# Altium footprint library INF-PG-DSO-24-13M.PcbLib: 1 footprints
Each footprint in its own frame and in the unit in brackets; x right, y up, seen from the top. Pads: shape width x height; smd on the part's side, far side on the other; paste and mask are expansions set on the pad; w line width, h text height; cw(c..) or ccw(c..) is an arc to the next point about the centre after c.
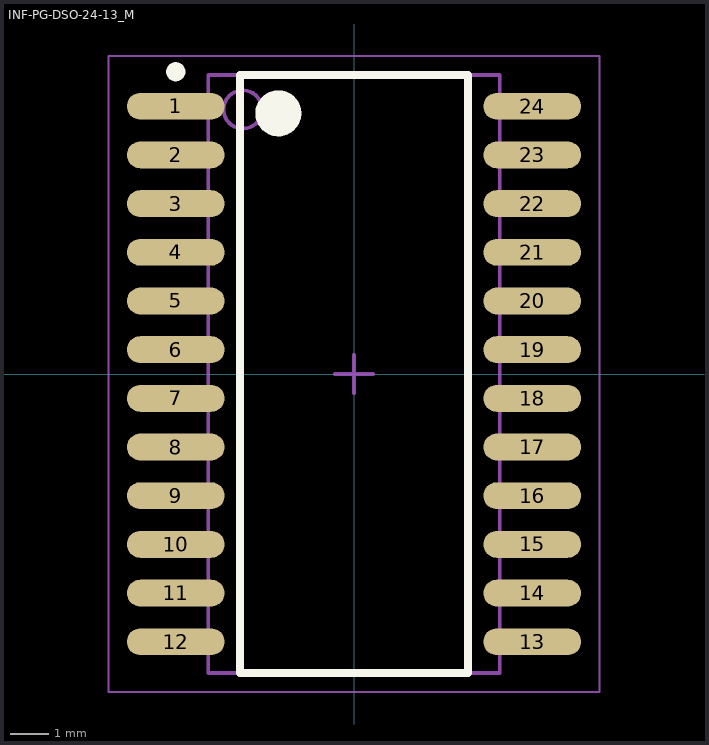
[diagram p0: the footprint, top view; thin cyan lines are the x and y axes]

## INF-PG-DSO-24-13_M [mm] "SOP, 24-Leads, Body 15.4x7.5mm, Pitch 1.27mm, IPC Low Density"
height 2.65
pads (24):
  oval 2.55x0.7 smd: 1(-4.65,6.985) 2(-4.65,5.715) 3(-4.65,4.445) 4(-4.65,3.175) 5(-4.65,1.905) 6(-4.65,0.635) 7(-4.65,-0.635) 8(-4.65,-1.905) 9(-4.65,-3.175) 10(-4.65,-4.445) 11(-4.65,-5.715) 12(-4.65,-6.985) 13(4.65,-6.985) 14(4.65,-5.715) 15(4.65,-4.445) 16(4.65,-3.175) 17(4.65,-1.905) 18(4.65,-0.635) 19(4.65,0.635) 20(4.65,1.905) 21(4.65,3.175) 22(4.65,4.445) 23(4.65,5.715) 24(4.65,6.985)
Top Overlay:
  circle w0.25: c-4.65,7.885 r0.125
  circle w0.6: c-1.975,6.8 r0.3
  lines w0.2: -2.975,-7.8 -2.975,7.8 2.975,7.8 2.975,-7.8 -2.975,-7.8
Mechanical 13:
  circle w0.1: c-2.9,6.9 r0.5
  lines w0.1: -3.8,-7.8 -3.8,7.8 3.8,7.8 3.8,-7.8 -3.8,-7.8
Mechanical 15:
  lines w0.05: -6.4,-8.3 -6.4,8.3 6.4,8.3 6.4,-8.3 -6.4,-8.3
  lines w0.1: -0.5,0 0.5,0 ; 0,-0.5 0,0.5
3D body: height 2.65, standoff 0.1, extent -3.8,-7.8 3.8,7.8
